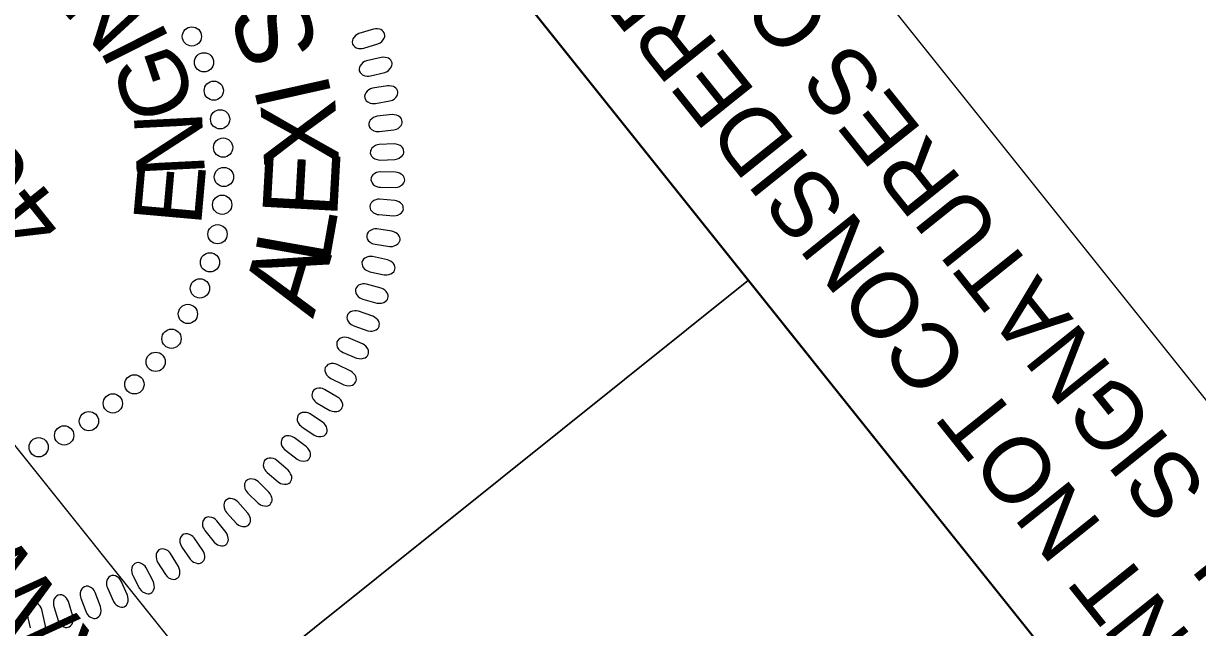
# Model space of a CAD drawing. Extents: x 473437 to 475344, y 504319 to 506318.
# Drawn here: x 473584.9 to 473682.6, y 505621 to 505671.2 of the extents above; entities that cross this region are included whole.
import ezdxf

# ---------------------------------------------------------------- set-up
doc = ezdxf.new("R2010")
doc.units = 0
for name, color, linetype in [('Sheet PE Seal Cell', 7, 'Continuous'), ('Sheet Plan CELL', 7, 'Continuous'), ('Sheet Sticker Exception Certification CELL', 7, 'Continuous'), ('Sheet Sticker Incomplete CELL', 7, 'Continuous')]:
    doc.layers.add(name, color=color, linetype=linetype)

msp = doc.modelspace()

# ---------------------------------------------------------------- linework, layer by layer
at = {"layer": 'Sheet PE Seal Cell'}
for points in [[(473613.221, 505669.135), (473614.394, 505669.494), (473614.593, 505669.594), (473614.712, 505669.685), (473614.841, 505669.842), (473614.917, 505669.967), (473614.96, 505670.098), (473614.968, 505670.209), (473614.954, 505670.323), (473614.902, 505670.424), (473614.838, 505670.53), (473614.751, 505670.612), (473614.624, 505670.683), (473614.531, 505670.717), (473614.368, 505670.737), (473614.179, 505670.742), (473614.02, 505670.717), (473612.816, 505670.355), (473612.661, 505670.284), (473612.541, 505670.2), (473612.414, 505670.068), (473612.313, 505669.92), (473612.266, 505669.803), (473612.254, 505669.635), (473612.279, 505669.486), (473612.362, 505669.356), (473612.44, 505669.27), (473612.572, 505669.178), (473612.77, 505669.113), (473612.961, 505669.102), (473613.093, 505669.111)], [(473613.764, 505666.843), (473614.957, 505667.129), (473615.161, 505667.216), (473615.285, 505667.299), (473615.424, 505667.448), (473615.508, 505667.568), (473615.559, 505667.696), (473615.574, 505667.806), (473615.567, 505667.921), (473615.521, 505668.025), (473615.465, 505668.134), (473615.383, 505668.222), (473615.261, 505668.301), (473615.169, 505668.341), (473615.008, 505668.371), (473614.82, 505668.388), (473614.659, 505668.373), (473613.436, 505668.087), (473613.276, 505668.026), (473613.151, 505667.949), (473613.016, 505667.826), (473612.906, 505667.684), (473612.852, 505667.571), (473612.83, 505667.404), (473612.845, 505667.254), (473612.918, 505667.118), (473612.992, 505667.027), (473613.118, 505666.927), (473613.31, 505666.851), (473613.502, 505666.827), (473613.634, 505666.828)], [(473614.187, 505664.544), (473615.395, 505664.754), (473615.605, 505664.829), (473615.734, 505664.904), (473615.882, 505665.043), (473615.973, 505665.158), (473616.033, 505665.282), (473616.054, 505665.392), (473616.054, 505665.506), (473616.016, 505665.612), (473615.966, 505665.725), (473615.889, 505665.819), (473615.772, 505665.904), (473615.684, 505665.95), (473615.525, 505665.991), (473615.338, 505666.019), (473615.177, 505666.014), (473613.937, 505665.806), (473613.775, 505665.754), (473613.644, 505665.686), (473613.503, 505665.571), (473613.384, 505665.437), (473613.322, 505665.327), (473613.29, 505665.162), (473613.296, 505665.011), (473613.361, 505664.871), (473613.428, 505664.776), (473613.548, 505664.668), (473613.735, 505664.58), (473613.924, 505664.544), (473614.056, 505664.536)], [(473614.498, 505662.209), (473615.718, 505662.343), (473615.932, 505662.404), (473616.065, 505662.471), (473616.222, 505662.601), (473616.32, 505662.709), (473616.387, 505662.83), (473616.416, 505662.938), (473616.423, 505663.052), (473616.391, 505663.161), (473616.349, 505663.277), (473616.277, 505663.374), (473616.167, 505663.467), (473616.081, 505663.518), (473615.925, 505663.569), (473615.74, 505663.608), (473615.579, 505663.614), (473614.329, 505663.484), (473614.163, 505663.443), (473614.029, 505663.383), (473613.88, 505663.277), (473613.754, 505663.15), (473613.685, 505663.044), (473613.642, 505662.882), (473613.639, 505662.732), (473613.695, 505662.587), (473613.756, 505662.488), (473613.868, 505662.373), (473614.05, 505662.273), (473614.237, 505662.225), (473614.368, 505662.21)], [(473614.584, 505659.841), (473615.809, 505659.899), (473616.026, 505659.946), (473616.164, 505660.005), (473616.328, 505660.124), (473616.433, 505660.227), (473616.508, 505660.343), (473616.543, 505660.449), (473616.557, 505660.562), (473616.532, 505660.673), (473616.496, 505660.791), (473616.432, 505660.893), (473616.327, 505660.992), (473616.245, 505661.049), (473616.092, 505661.108), (473615.91, 505661.16), (473615.75, 505661.175), (473614.495, 505661.124), (473614.326, 505661.094), (473614.189, 505661.043), (473614.034, 505660.946), (473613.899, 505660.828), (473613.824, 505660.727), (473613.771, 505660.567), (473613.758, 505660.417), (473613.805, 505660.269), (473613.86, 505660.167), (473613.965, 505660.045), (473614.14, 505659.934), (473614.323, 505659.874), (473614.454, 505659.851)], [(473614.603, 505657.576), (473615.83, 505657.555), (473616.05, 505657.59), (473616.19, 505657.639), (473616.362, 505657.748), (473616.473, 505657.844), (473616.555, 505657.955), (473616.597, 505658.059), (473616.618, 505658.171), (473616.6, 505658.282), (473616.572, 505658.403), (473616.514, 505658.508), (473616.415, 505658.615), (473616.337, 505658.676), (473616.189, 505658.746), (473616.01, 505658.809), (473615.851, 505658.834), (473614.595, 505658.862), (473614.425, 505658.842), (473614.284, 505658.799), (473614.123, 505658.713), (473613.982, 505658.603), (473613.9, 505658.507), (473613.838, 505658.351), (473613.816, 505658.202), (473613.853, 505658.052), (473613.902, 505657.946), (473613.999, 505657.817), (473614.166, 505657.695), (473614.345, 505657.624), (473614.474, 505657.593)], [(473614.464, 505655.3), (473615.687, 505655.203), (473615.909, 505655.223), (473616.052, 505655.264), (473616.23, 505655.362), (473616.348, 505655.451), (473616.436, 505655.556), (473616.483, 505655.657), (473616.512, 505655.767), (473616.501, 505655.88), (473616.481, 505656.002), (473616.43, 505656.111), (473616.338, 505656.223), (473616.264, 505656.289), (473616.12, 505656.369), (473615.946, 505656.442), (473615.789, 505656.478), (473614.536, 505656.584), (473614.366, 505656.575), (473614.223, 505656.541), (473614.057, 505656.465), (473613.909, 505656.364), (473613.822, 505656.274), (473613.749, 505656.122), (473613.718, 505655.974), (473613.746, 505655.822), (473613.787, 505655.714), (473613.876, 505655.579), (473614.036, 505655.447), (473614.21, 505655.365), (473614.337, 505655.325)], [(473614.16, 505652.834), (473615.375, 505652.66), (473615.597, 505652.666), (473615.743, 505652.698), (473615.927, 505652.785), (473616.049, 505652.866), (473616.144, 505652.966), (473616.198, 505653.064), (473616.234, 505653.172), (473616.23, 505653.286), (473616.217, 505653.408), (473616.173, 505653.52), (473616.088, 505653.638), (473616.018, 505653.708), (473615.88, 505653.797), (473615.71, 505653.881), (473615.556, 505653.926), (473614.313, 505654.111), (473614.142, 505654.113), (473613.997, 505654.088), (473613.827, 505654.023), (473613.673, 505653.931), (473613.58, 505653.846), (473613.498, 505653.699), (473613.458, 505653.554), (473613.476, 505653.4), (473613.511, 505653.29), (473613.591, 505653.15), (473613.742, 505653.007), (473613.91, 505652.915), (473614.034, 505652.868)], [(473613.721, 505650.549), (473614.923, 505650.299), (473615.145, 505650.291), (473615.292, 505650.313), (473615.481, 505650.389), (473615.608, 505650.462), (473615.709, 505650.555), (473615.77, 505650.649), (473615.812, 505650.756), (473615.815, 505650.869), (473615.81, 505650.992), (473615.773, 505651.107), (473615.696, 505651.229), (473615.631, 505651.304), (473615.498, 505651.401), (473615.334, 505651.496), (473615.183, 505651.551), (473613.954, 505651.814), (473613.783, 505651.826), (473613.638, 505651.81), (473613.463, 505651.755), (473613.303, 505651.674), (473613.206, 505651.595), (473613.115, 505651.454), (473613.065, 505651.311), (473613.074, 505651.157), (473613.102, 505651.044), (473613.173, 505650.899), (473613.314, 505650.748), (473613.477, 505650.645), (473613.598, 505650.59)], [(473613.129, 505648.278), (473614.313, 505647.953), (473614.534, 505647.931), (473614.683, 505647.943), (473614.876, 505648.008), (473615.007, 505648.072), (473615.114, 505648.159), (473615.18, 505648.249), (473615.23, 505648.353), (473615.24, 505648.466), (473615.242, 505648.589), (473615.212, 505648.706), (473615.144, 505648.833), (473615.082, 505648.912), (473614.956, 505649.017), (473614.799, 505649.122), (473614.651, 505649.186), (473613.442, 505649.525), (473613.272, 505649.548), (473613.125, 505649.542), (473612.948, 505649.498), (473612.784, 505649.427), (473612.681, 505649.354), (473612.581, 505649.219), (473612.523, 505649.079), (473612.522, 505648.925), (473612.542, 505648.811), (473612.604, 505648.662), (473612.736, 505648.502), (473612.892, 505648.389), (473613.008, 505648.326)], [(473612.385, 505646.047), (473613.546, 505645.649), (473613.765, 505645.612), (473613.914, 505645.617), (473614.111, 505645.668), (473614.246, 505645.724), (473614.358, 505645.804), (473614.43, 505645.89), (473614.485, 505645.99), (473614.502, 505646.102), (473614.513, 505646.225), (473614.491, 505646.344), (473614.43, 505646.475), (473614.374, 505646.557), (473614.254, 505646.67), (473614.104, 505646.784), (473613.961, 505646.857), (473612.775, 505647.273), (473612.607, 505647.307), (473612.46, 505647.309), (473612.28, 505647.276), (473612.112, 505647.216), (473612.005, 505647.149), (473611.897, 505647.02), (473611.83, 505646.885), (473611.819, 505646.731), (473611.832, 505646.616), (473611.885, 505646.463), (473612.007, 505646.295), (473612.155, 505646.173), (473612.268, 505646.103)], [(473611.488, 505643.848), (473612.621, 505643.377), (473612.838, 505643.328), (473612.987, 505643.322), (473613.186, 505643.361), (473613.326, 505643.409), (473613.442, 505643.482), (473613.519, 505643.563), (473613.58, 505643.659), (473613.604, 505643.77), (473613.622, 505643.892), (473613.608, 505644.011), (473613.555, 505644.147), (473613.505, 505644.232), (473613.393, 505644.352), (473613.25, 505644.476), (473613.111, 505644.558), (473611.953, 505645.047), (473611.788, 505645.091), (473611.642, 505645.102), (473611.46, 505645.081), (473611.289, 505645.031), (473611.177, 505644.972), (473611.062, 505644.85), (473610.986, 505644.719), (473610.966, 505644.566), (473610.972, 505644.45), (473611.015, 505644.295), (473611.126, 505644.119), (473611.266, 505643.988), (473611.374, 505643.911)], [(473610.465, 505641.687), (473611.566, 505641.147), (473611.779, 505641.084), (473611.928, 505641.069), (473612.13, 505641.095), (473612.271, 505641.134), (473612.392, 505641.2), (473612.474, 505641.276), (473612.541, 505641.368), (473612.572, 505641.477), (473612.598, 505641.598), (473612.591, 505641.718), (473612.547, 505641.856), (473612.502, 505641.945), (473612.398, 505642.071), (473612.262, 505642.204), (473612.129, 505642.294), (473611.005, 505642.855), (473610.842, 505642.909), (473610.698, 505642.931), (473610.515, 505642.92), (473610.34, 505642.882), (473610.225, 505642.829), (473610.102, 505642.715), (473610.018, 505642.589), (473609.989, 505642.438), (473609.988, 505642.321), (473610.02, 505642.163), (473610.121, 505641.982), (473610.252, 505641.842), (473610.355, 505641.758)], [(473609.341, 505639.636), (473610.406, 505639.027), (473610.616, 505638.95), (473610.762, 505638.926), (473610.965, 505638.94), (473611.109, 505638.97), (473611.234, 505639.028), (473611.32, 505639.098), (473611.393, 505639.186), (473611.431, 505639.293), (473611.465, 505639.412), (473611.465, 505639.532), (473611.43, 505639.672), (473611.39, 505639.764), (473611.294, 505639.897), (473611.168, 505640.037), (473611.04, 505640.136), (473609.953, 505640.767), (473609.795, 505640.832), (473609.651, 505640.861), (473609.468, 505640.863), (473609.291, 505640.835), (473609.174, 505640.79), (473609.044, 505640.683), (473608.952, 505640.563), (473608.913, 505640.414), (473608.905, 505640.298), (473608.928, 505640.138), (473609.016, 505639.951), (473609.138, 505639.803), (473609.236, 505639.713)], [(473608.068, 505637.646), (473609.093, 505636.971), (473609.297, 505636.882), (473609.442, 505636.848), (473609.646, 505636.849), (473609.791, 505636.87), (473609.919, 505636.92), (473610.01, 505636.985), (473610.088, 505637.068), (473610.133, 505637.172), (473610.174, 505637.289), (473610.181, 505637.409), (473610.155, 505637.551), (473610.122, 505637.645), (473610.034, 505637.784), (473609.917, 505637.932), (473609.796, 505638.039), (473608.75, 505638.736), (473608.596, 505638.81), (473608.455, 505638.849), (473608.273, 505638.862), (473608.094, 505638.845), (473607.974, 505638.808), (473607.838, 505638.71), (473607.739, 505638.595), (473607.69, 505638.449), (473607.674, 505638.334), (473607.687, 505638.174), (473607.763, 505637.98), (473607.876, 505637.825), (473607.969, 505637.729)], [(473606.694, 505635.708), (473607.674, 505634.97), (473607.872, 505634.869), (473608.015, 505634.826), (473608.218, 505634.814), (473608.364, 505634.826), (473608.495, 505634.868), (473608.59, 505634.927), (473608.673, 505635.005), (473608.725, 505635.106), (473608.772, 505635.22), (473608.788, 505635.339), (473608.771, 505635.483), (473608.743, 505635.579), (473608.664, 505635.722), (473608.556, 505635.878), (473608.443, 505635.992), (473607.443, 505636.754), (473607.294, 505636.838), (473607.155, 505636.885), (473606.974, 505636.909), (473606.795, 505636.904), (473606.673, 505636.874), (473606.53, 505636.785), (473606.425, 505636.677), (473606.367, 505636.534), (473606.344, 505636.42), (473606.347, 505636.258), (473606.411, 505636.062), (473606.514, 505635.899), (473606.6, 505635.798)], [(473605.166, 505633.871), (473606.098, 505633.073), (473606.289, 505632.959), (473606.428, 505632.907), (473606.631, 505632.883), (473606.777, 505632.885), (473606.911, 505632.919), (473607.009, 505632.972), (473607.097, 505633.044), (473607.155, 505633.143), (473607.209, 505633.253), (473607.233, 505633.371), (473607.224, 505633.516), (473607.203, 505633.613), (473607.133, 505633.762), (473607.035, 505633.924), (473606.929, 505634.044), (473605.979, 505634.867), (473605.835, 505634.96), (473605.7, 505635.017), (473605.521, 505635.052), (473605.341, 505635.058), (473605.218, 505635.036), (473605.07, 505634.956), (473604.958, 505634.855), (473604.891, 505634.715), (473604.861, 505634.603), (473604.854, 505634.442), (473604.905, 505634.241), (473604.998, 505634.073), (473605.077, 505633.967)], [(473603.558, 505632.157), (473604.438, 505631.303), (473604.622, 505631.177), (473604.759, 505631.117), (473604.959, 505631.079), (473605.105, 505631.073), (473605.241, 505631.098), (473605.342, 505631.145), (473605.435, 505631.212), (473605.498, 505631.306), (473605.56, 505631.413), (473605.59, 505631.529), (473605.591, 505631.674), (473605.575, 505631.773), (473605.515, 505631.925), (473605.428, 505632.093), (473605.329, 505632.22), (473604.433, 505633.101), (473604.296, 505633.203), (473604.164, 505633.268), (473603.987, 505633.315), (473603.809, 505633.332), (473603.684, 505633.318), (473603.531, 505633.246), (473603.413, 505633.153), (473603.337, 505633.018), (473603.3, 505632.908), (473603.283, 505632.747), (473603.322, 505632.544), (473603.404, 505632.37), (473603.476, 505632.258)], [(473601.802, 505630.541), (473602.627, 505629.633), (473602.802, 505629.496), (473602.935, 505629.427), (473603.132, 505629.377), (473603.278, 505629.361), (473603.415, 505629.378), (473603.518, 505629.418), (473603.615, 505629.48), (473603.684, 505629.569), (473603.753, 505629.673), (473603.79, 505629.786), (473603.8, 505629.931), (473603.791, 505630.03), (473603.74, 505630.186), (473603.664, 505630.359), (473603.574, 505630.492), (473602.734, 505631.427), (473602.603, 505631.538), (473602.476, 505631.611), (473602.302, 505631.668), (473602.126, 505631.697), (473602, 505631.691), (473601.844, 505631.629), (473601.72, 505631.543), (473601.636, 505631.413), (473601.591, 505631.306), (473601.565, 505631.147), (473601.59, 505630.941), (473601.661, 505630.763), (473601.726, 505630.646)], [(473599.994, 505629.027), (473600.761, 505628.069), (473600.927, 505627.921), (473601.055, 505627.844), (473601.248, 505627.782), (473601.393, 505627.757), (473601.53, 505627.765), (473601.637, 505627.799), (473601.737, 505627.854), (473601.812, 505627.939), (473601.887, 505628.037), (473601.931, 505628.149), (473601.95, 505628.293), (473601.947, 505628.392), (473601.906, 505628.551), (473601.841, 505628.729), (473601.759, 505628.867), (473600.98, 505629.854), (473600.857, 505629.972), (473600.734, 505630.053), (473600.564, 505630.121), (473600.39, 505630.16), (473600.264, 505630.162), (473600.104, 505630.111), (473599.975, 505630.033), (473599.883, 505629.908), (473599.833, 505629.804), (473599.795, 505629.647), (473599.808, 505629.439), (473599.867, 505629.257), (473599.925, 505629.137)], [(473598.078, 505627.66), (473598.782, 505626.655), (473598.939, 505626.497), (473599.062, 505626.412), (473599.251, 505626.338), (473599.394, 505626.304), (473599.531, 505626.303), (473599.64, 505626.331), (473599.743, 505626.379), (473599.823, 505626.46), (473599.904, 505626.553), (473599.955, 505626.662), (473599.984, 505626.803), (473599.987, 505626.903), (473599.956, 505627.064), (473599.902, 505627.246), (473599.829, 505627.389), (473599.113, 505628.422), (473598.997, 505628.548), (473598.881, 505628.636), (473598.715, 505628.715), (473598.544, 505628.766), (473598.418, 505628.775), (473598.255, 505628.734), (473598.121, 505628.664), (473598.022, 505628.546), (473597.965, 505628.445), (473597.918, 505628.29), (473597.918, 505628.083), (473597.965, 505627.897), (473598.016, 505627.774)], [(473596.069, 505626.419), (473596.709, 505625.372), (473596.855, 505625.204), (473596.972, 505625.112), (473597.157, 505625.026), (473597.297, 505624.983), (473597.434, 505624.974), (473597.544, 505624.994), (473597.651, 505625.036), (473597.735, 505625.111), (473597.822, 505625.2), (473597.88, 505625.305), (473597.917, 505625.445), (473597.926, 505625.544), (473597.906, 505625.707), (473597.863, 505625.891), (473597.799, 505626.039), (473597.15, 505627.115), (473597.042, 505627.248), (473596.931, 505627.343), (473596.772, 505627.433), (473596.603, 505627.493), (473596.478, 505627.51), (473596.313, 505627.48), (473596.175, 505627.419), (473596.069, 505627.307), (473596.005, 505627.209), (473595.949, 505627.058), (473595.935, 505626.851), (473595.972, 505626.663), (473596.014, 505626.537)], [(473593.999, 505625.301), (473594.572, 505624.216), (473594.708, 505624.04), (473594.819, 505623.94), (473594.998, 505623.843), (473595.135, 505623.791), (473595.272, 505623.773), (473595.382, 505623.787), (473595.491, 505623.821), (473595.58, 505623.891), (473595.672, 505623.974), (473595.737, 505624.075), (473595.783, 505624.213), (473595.798, 505624.311), (473595.788, 505624.475), (473595.757, 505624.662), (473595.703, 505624.813), (473595.122, 505625.928), (473595.023, 505626.067), (473594.917, 505626.169), (473594.764, 505626.268), (473594.6, 505626.34), (473594.476, 505626.365), (473594.31, 505626.344), (473594.168, 505626.292), (473594.054, 505626.187), (473593.986, 505626.094), (473593.919, 505625.947), (473593.893, 505625.741), (473593.917, 505625.55), (473593.952, 505625.422)], [(473591.887, 505624.265), (473592.392, 505623.147), (473592.516, 505622.962), (473592.62, 505622.856), (473592.792, 505622.748), (473592.926, 505622.688), (473593.061, 505622.66), (473593.173, 505622.668), (473593.284, 505622.695), (473593.377, 505622.759), (473593.474, 505622.836), (473593.545, 505622.933), (473593.599, 505623.067), (473593.621, 505623.165), (473593.621, 505623.329), (473593.602, 505623.517), (473593.557, 505623.672), (473593.048, 505624.821), (473592.957, 505624.966), (473592.859, 505625.075), (473592.712, 505625.183), (473592.553, 505625.265), (473592.431, 505625.297), (473592.263, 505625.288), (473592.119, 505625.244), (473591.999, 505625.147), (473591.924, 505625.058), (473591.849, 505624.915), (473591.809, 505624.711), (473591.822, 505624.52), (473591.848, 505624.389)], [(473589.686, 505623.406), (473590.119, 505622.258), (473590.232, 505622.066), (473590.329, 505621.953), (473590.494, 505621.834), (473590.624, 505621.766), (473590.757, 505621.731), (473590.868, 505621.731), (473590.981, 505621.752), (473591.078, 505621.81), (473591.18, 505621.88), (473591.256, 505621.972), (473591.32, 505622.103), (473591.347, 505622.199), (473591.358, 505622.363), (473591.35, 505622.551), (473591.315, 505622.709), (473590.879, 505623.888), (473590.798, 505624.038), (473590.706, 505624.153), (473590.566, 505624.271), (473590.412, 505624.361), (473590.293, 505624.403), (473590.125, 505624.403), (473589.978, 505624.369), (473589.852, 505624.278), (473589.773, 505624.195), (473589.688, 505624.057), (473589.636, 505623.856), (473589.637, 505623.664), (473589.654, 505623.532)], [(473587.429, 505622.722), (473587.789, 505621.549), (473587.89, 505621.35), (473587.98, 505621.232), (473588.137, 505621.103), (473588.262, 505621.026), (473588.393, 505620.983), (473588.505, 505620.976), (473588.618, 505620.989), (473588.719, 505621.042), (473588.825, 505621.105), (473588.907, 505621.193), (473588.978, 505621.319), (473589.012, 505621.413), (473589.032, 505621.576), (473589.036, 505621.765), (473589.011, 505621.924), (473588.65, 505623.127), (473588.579, 505623.282), (473588.495, 505623.403), (473588.363, 505623.529), (473588.214, 505623.63), (473588.098, 505623.678), (473587.93, 505623.689), (473587.782, 505623.664), (473587.651, 505623.582), (473587.565, 505623.504), (473587.473, 505623.371), (473587.408, 505623.174), (473587.397, 505622.982), (473587.406, 505622.849)]]:
    msp.add_lwpolyline(points, close=True, dxfattribs=at)
msp.add_lwpolyline([(473586.716, 505620.886), (473586.732, 505621.075), (473586.717, 505621.235), (473586.432, 505622.46), (473586.37, 505622.619), (473586.294, 505622.744), (473586.17, 505622.879), (473586.028, 505622.988), (473585.916, 505623.043), (473585.749, 505623.065), (473585.599, 505623.05), (473585.463, 505622.976), (473585.372, 505622.903), (473585.272, 505622.777), (473585.195, 505622.584), (473585.172, 505622.394), (473585.173, 505622.26), (473585.188, 505622.131), (473585.474, 505620.938)], dxfattribs=at)
for centre in [(473598.918, 505670.117), (473599.925, 505667.966), (473600.738, 505665.609), (473601.266, 505663.227), (473601.514, 505660.876), (473601.581, 505658.432), (473601.437, 505656.124), (473601.051, 505653.674), (473600.421, 505651.335), (473599.587, 505649.171), (473598.585, 505647.044), (473597.222, 505644.985), (473595.902, 505643.063), (473594.135, 505641.19), (473592.343, 505639.604), (473590.351, 505638.133), (473588.291, 505636.945), (473586.17, 505635.962)]:
    msp.add_circle(centre, 0.801, dxfattribs=at)
at = {"layer": 'Sheet Plan CELL'}
msp.add_line((473557.377, 505579.55), (473645.174, 505649.832), dxfattribs=at)
for points in [[(473557.377, 505579.55), (473494.89, 505657.607), (473582.726, 505727.92), (473645.22, 505649.853)], [(473619.893, 505501.436), (473557.377, 505579.55), (473645.22, 505649.853), (473707.709, 505571.734)]]:
    msp.add_lwpolyline(points, close=True, dxfattribs=at)
at = {"layer": 'Sheet Sticker Exception Certification CELL'}
for p, q in [((473601.063, 505742.596), (473726.057, 505586.418)), ((473601.063, 505742.596), (473726.057, 505586.418)), ((473707.709, 505571.734), (473582.716, 505727.912)), ((473707.709, 505571.734), (473582.716, 505727.912))]:
    msp.add_line(p, q, dxfattribs=at)
at = {"layer": 'Sheet Sticker Incomplete CELL'}
msp.add_lwpolyline([(473647.22, 505557.313), (473628.873, 505542.629), (473537.02, 505657.398), (473555.367, 505672.082)], close=True, dxfattribs=at)

# ---------------------------------------------------------------- texts
at = {"layer": 'Sheet PE Seal Cell'}
for s, height, rotation, p in [('N', 5.669, 132.5756, (473595.825, 505672.203)), ('S', 6.236, 109.45864, (473609.644, 505668.978)), ('46155', 6.2363, 128.65259, (473588.84, 505654.883)), ('I', 5.669, 116.696, (473597.176, 505669.758)), ('G', 5.669, 108.7562, (473599.374, 505664.308)), ('I', 6.236, 102.61298, (473610.606, 505665.065)), ('X', 6.236, 93.66566, (473611.184, 505659.445)), ('N', 5.669, 92.87661, (473600.013, 505658.551)), ('E', 6.236, 86.82, (473610.989, 505654.932)), ('E', 5.669, 84.93681, (473599.665, 505654.257)), ('L', 6.236, 79.97435, (473610.278, 505650.888)), ('A', 6.236, 73.35467, (473608.992, 505646.605))]:
    msp.add_text(s, height=height, rotation=rotation, dxfattribs=at).set_placement(p)
at = {"layer": 'Sheet Sticker Exception Certification CELL'}
for s, p in [('UNLESS ALL SIGNATURES COMPLETED', (473712.66, 505596.189)), ('UNLESS ALL SIGNATURES COMPLETED', (473712.66, 505596.189)), ('DOCUMENT NOT CONSIDERED FINAL', (473702.62, 505594.649)), ('DOCUMENT NOT CONSIDERED FINAL', (473702.62, 505594.649))]:
    msp.add_text(s, height=5.5, rotation=128.67122, dxfattribs=at).set_placement(p)
at = {"layer": 'Sheet Sticker Incomplete CELL'}
for s, height, p in [('INCOMPLETE PLANS', 11.52, (473632.493, 505556.99)), ('DO NOT USE FOR R/W ACQUISITION', 5.76, (473635.889, 505563.87))]:
    msp.add_text(s, height=height, rotation=128.67122, dxfattribs=at).set_placement(p)

doc.saveas('drawing.dxf')
